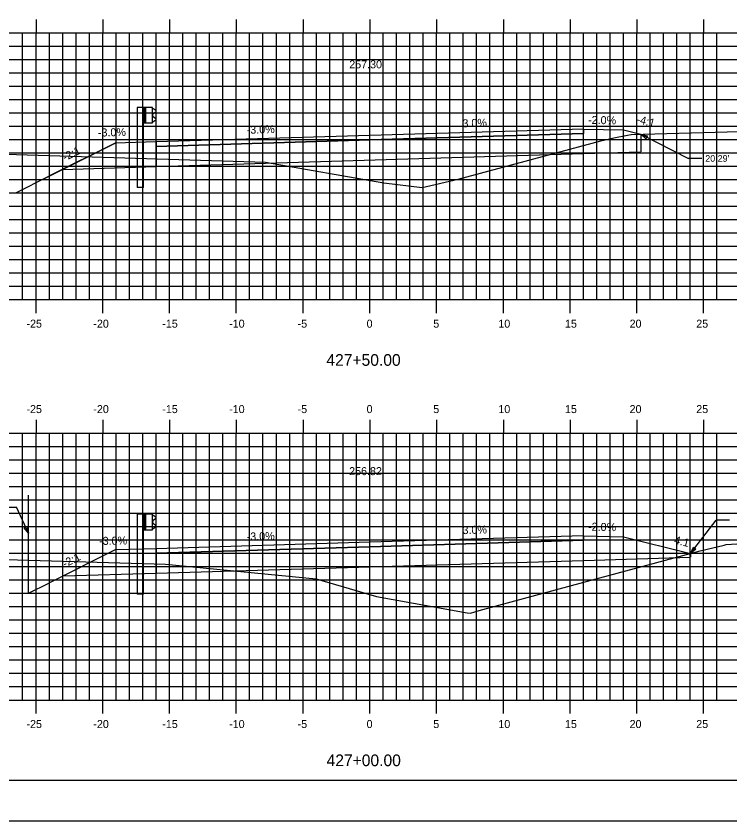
# Model space of a CAD drawing. Extents: x 1160718 to 1173142, y 616002 to 617630.
# Drawn here: x 1170822.9 to 1170876.4, y 616613.9 to 616674.2 of the extents above; entities that cross this region are included whole.
import ezdxf

# ---------------------------------------------------------------- set-up
doc = ezdxf.new("R2010")
doc.units = 0
for name, color, linetype in [('ANNOTATION', 7, 'Continuous'), ('BORDER', 7, 'Continuous'), ('D_Guardrail_Beam_Lt', 7, 'Continuous'), ('D_Roadway_Centerline', 7, 'Continuous'), ('D_Roadway_Centerline_Text', 7, 'Continuous'), ('D_Roadway_Edge_Pavement', 7, 'Continuous'), ('D_Roadway_Edge_Shoulder', 7, 'Continuous'), ('D_Roadway_Edge_TW', 7, 'Continuous'), ('D_Roadway_Pavement', 7, 'Continuous'), ('D_Roadway_SlopeLines', 7, 'Continuous'), ('D_Roadway_SubGrade', 7, 'Continuous'), ('H_V ANNOTATION', 7, 'Continuous'), ('MAJOR', 7, 'Continuous'), ('MINOR', 7, 'Continuous'), ('PLOT BOUNDARY', 7, 'Continuous'), ('S_Roadway_Centerline', 7, 'Continuous'), ('SHADING', 7, 'Continuous')]:
    doc.layers.add(name, color=color, linetype=linetype)

msp = doc.modelspace()

# ---------------------------------------------------------------- linework, layer by layer
at = {"layer": 'ANNOTATION'}
for p, q in [((1170869.707, 616665.327), (1170873.292, 616663.506)), ((1170874.292, 616663.506), (1170873.292, 616663.506)), ((1170821.96, 616637.377), (1170822.96, 616637.377)), ((1170823.863, 616635.436), (1170822.96, 616637.377)), ((1170873.445, 616633.911), (1170875.353, 616636.405)), ((1170876.353, 616636.405), (1170875.353, 616636.405))]:
    msp.add_line(p, q, dxfattribs=at)
for points in [[(1170870.096, 616664.989), (1170869.707, 616665.327), (1170870.209, 616665.212)], [(1170823.765, 616635.942), (1170823.863, 616635.436), (1170823.538, 616635.837)], [(1170873.848, 616634.232), (1170873.445, 616633.911), (1170873.649, 616634.384)]]:
    msp.add_lwpolyline(points, close=True, dxfattribs=at)
at = {"layer": 'BORDER'}
msp.add_line((1170774.42, 616616.928), (1170934.42, 616616.928), dxfattribs=at)
at = {"layer": 'D_Guardrail_Beam_Lt'}
for p, q in [((1170831.99, 616667.332), (1170831.99, 616661.332)), ((1170832.461, 616667.332), (1170831.99, 616667.332)), ((1170833.148, 616667.332), (1170832.461, 616667.332)), ((1170832.461, 616667.332), (1170832.461, 616666.165)), ((1170832.523, 616667.332), (1170832.523, 616666.165)), ((1170832.627, 616667.332), (1170832.627, 616666.165)), ((1170833.148, 616666.165), (1170833.148, 616667.332)), ((1170833.148, 616667.249), (1170833.222, 616667.234)), ((1170833.382, 616666.984), (1170833.186, 616666.848)), ((1170833.238, 616667.227), (1170833.382, 616667.127)), ((1170833.222, 616666.263), (1170833.148, 616666.249)), ((1170833.152, 616666.784), (1170833.152, 616666.714)), ((1170833.186, 616666.649), (1170833.382, 616666.513)), ((1170833.382, 616666.37), (1170833.238, 616666.27)), ((1170832.461, 616666.165), (1170833.148, 616666.165)), ((1170832.481, 616661.332), (1170832.481, 616666.165)), ((1170832.481, 616661.332), (1170831.99, 616661.332)), ((1170831.989, 616636.851), (1170831.989, 616630.851)), ((1170832.46, 616636.851), (1170831.989, 616636.851)), ((1170833.148, 616636.851), (1170832.46, 616636.851)), ((1170832.46, 616636.851), (1170832.46, 616635.684)), ((1170832.523, 616636.851), (1170832.523, 616635.684)), ((1170832.627, 616636.851), (1170832.627, 616635.684)), ((1170833.148, 616635.684), (1170833.148, 616636.851)), ((1170833.148, 616636.767), (1170833.222, 616636.753)), ((1170833.238, 616636.746), (1170833.381, 616636.646)), ((1170833.152, 616636.302), (1170833.152, 616636.232)), ((1170833.381, 616636.503), (1170833.186, 616636.367)), ((1170833.186, 616636.168), (1170833.381, 616636.032)), ((1170832.46, 616635.684), (1170833.148, 616635.684)), ((1170832.481, 616630.851), (1170832.481, 616635.684)), ((1170833.222, 616635.782), (1170833.148, 616635.767)), ((1170833.381, 616635.888), (1170833.238, 616635.788)), ((1170832.481, 616630.851), (1170831.989, 616630.851))]:
    msp.add_line(p, q, dxfattribs=at)
for centre, major_axis, start_param, end_param in [((1170833.214, 616667.193), (0.0417, 0), 0.959931, 1.376053), ((1170833.331, 616667.056), (0.0877, 0), 5.323254, 7.243116), ((1170833.231, 616666.784), (-0.0789, 0), 5.323254, 6.283185), ((1170833.231, 616666.714), (-0.0789, 0), 6.283185, 7.243116), ((1170833.214, 616666.304), (0.0417, 0), 4.907132, 5.323254), ((1170833.331, 616666.441), (0.0877, 0), 5.323254, 7.243116), ((1170833.214, 616636.712), (0.0417, 0), 0.959931, 1.376053), ((1170833.231, 616636.302), (-0.0789, 0), 5.323254, 6.283185), ((1170833.231, 616636.232), (-0.0789, 0), 6.283185, 7.243116), ((1170833.331, 616636.574), (0.0877, 0), 5.323254, 7.243116), ((1170833.214, 616635.822), (0.0417, 0), 4.907132, 5.323254), ((1170833.331, 616635.96), (0.0877, 0), 5.323254, 7.243116)]:
    msp.add_ellipse(centre, major_axis=major_axis, ratio=0.995501, start_param=start_param, end_param=end_param, dxfattribs=at)
at = {"layer": 'D_Roadway_Centerline'}
for points in [[(1170822.9, 616660.928), (1170825.392, 616662.175), (1170830.356, 616664.657)], [(1170824.9, 616661.928), (1170824.9, 616661.928), (1170830.356, 616664.657)]]:
    msp.add_lwpolyline(points, dxfattribs=at)
at = {"layer": 'D_Roadway_Edge_Pavement'}
msp.add_lwpolyline([(1170779.42, 616630.928), (1170823.863, 616630.928), (1170825.392, 616631.693)], dxfattribs=at)
at = {"layer": 'D_Roadway_Edge_Shoulder'}
for points in [[(1170865.42, 616665.709), (1170865.42, 616665.375)], [(1170833.42, 616664.749), (1170833.42, 616664.415)], [(1170865.42, 616635.227), (1170865.42, 616634.894)], [(1170833.42, 616634.267), (1170833.42, 616633.934)]]:
    msp.add_lwpolyline(points, dxfattribs=at)
at = {"layer": 'D_Roadway_Edge_TW'}
for points in [[(1170865.42, 616665.375), (1170865.42, 616665.709), (1170849.42, 616665.229), (1170833.42, 616664.749), (1170833.42, 616664.415), (1170849.42, 616664.895)], [(1170865.42, 616634.894), (1170865.42, 616635.227), (1170849.42, 616634.747), (1170833.42, 616634.267), (1170833.42, 616633.934), (1170849.42, 616634.414)]]:
    msp.add_lwpolyline(points, close=True, dxfattribs=at)
at = {"layer": 'D_Roadway_Pavement'}
for p, q in [((1170833.42, 616664.749), (1170830.356, 616664.657)), ((1170823.863, 616630.928), (1170823.863, 616638.285)), ((1170833.42, 616634.267), (1170830.356, 616634.175))]:
    msp.add_line(p, q, dxfattribs=at)
for points in [[(1170865.42, 616665.375), (1170865.42, 616665.375), (1170849.42, 616664.895), (1170833.42, 616664.415), (1170833.42, 616664.415), (1170849.42, 616664.895)], [(1170865.42, 616634.894), (1170865.42, 616634.894), (1170849.42, 616634.414), (1170833.42, 616633.934), (1170833.42, 616633.934), (1170849.42, 616634.414)]]:
    msp.add_lwpolyline(points, close=True, dxfattribs=at)
for points in [[(1170865.42, 616665.375), (1170865.42, 616665.375)], [(1170865.42, 616665.375), (1170865.42, 616665.375)], [(1170833.42, 616664.415), (1170833.42, 616664.415)], [(1170833.42, 616664.415), (1170833.42, 616664.415)], [(1170865.42, 616634.894), (1170865.42, 616634.894)], [(1170865.42, 616634.894), (1170865.42, 616634.894)], [(1170833.42, 616633.934), (1170833.42, 616633.934)], [(1170833.42, 616633.934), (1170833.42, 616633.934)]]:
    msp.add_lwpolyline(points, dxfattribs=at)
at = {"layer": 'D_Roadway_SlopeLines'}
for points in [[(1170868.42, 616665.649), (1170869.707, 616665.327)], [(1170830.356, 616664.657), (1170824.9, 616661.928)], [(1170868.42, 616635.167), (1170873.445, 616633.911)]]:
    msp.add_lwpolyline(points, dxfattribs=at)
at = {"layer": 'D_Roadway_SubGrade'}
for p, q in [((1170865.42, 616665.709), (1170868.42, 616665.649)), ((1170865.42, 616663.876), (1170865.42, 616665.709)), ((1170865.42, 616665.375), (1170849.42, 616664.895)), ((1170865.42, 616663.876), (1170865.42, 616665.375)), ((1170868.42, 616665.649), (1170869.707, 616665.327)), ((1170869.707, 616665.327), (1170869.707, 616664.004)), ((1170830.356, 616664.657), (1170825.392, 616662.175)), ((1170849.42, 616664.895), (1170833.42, 616664.415)), ((1170833.42, 616662.916), (1170833.42, 616664.749)), ((1170833.42, 616664.415), (1170833.42, 616662.916)), ((1170865.42, 616635.227), (1170868.42, 616635.167)), ((1170865.42, 616633.394), (1170865.42, 616635.227)), ((1170868.42, 616635.167), (1170873.445, 616633.911)), ((1170849.42, 616634.414), (1170833.42, 616633.934)), ((1170865.42, 616634.894), (1170849.42, 616634.414)), ((1170865.42, 616633.394), (1170865.42, 616634.894)), ((1170830.356, 616634.175), (1170825.392, 616631.693)), ((1170833.42, 616632.434), (1170833.42, 616634.267)), ((1170833.42, 616633.934), (1170833.42, 616632.434)), ((1170873.445, 616633.911), (1170873.445, 616633.635))]:
    msp.add_line(p, q, dxfattribs=at)
at = {"layer": 'MAJOR'}
for p, q in [((1170824.42, 616673.93), (1170824.42, 616672.928)), ((1170829.42, 616673.93), (1170829.42, 616672.928)), ((1170834.42, 616673.93), (1170834.42, 616672.928)), ((1170839.42, 616673.93), (1170839.42, 616672.928)), ((1170844.42, 616673.93), (1170844.42, 616672.928)), ((1170849.42, 616673.93), (1170849.42, 616672.928)), ((1170854.42, 616673.93), (1170854.42, 616672.928)), ((1170859.42, 616673.93), (1170859.42, 616672.928)), ((1170864.42, 616673.93), (1170864.42, 616672.928)), ((1170869.42, 616673.93), (1170869.42, 616672.928)), ((1170874.42, 616673.93), (1170874.42, 616672.928)), ((1170779.42, 616672.928), (1170919.42, 616672.928)), ((1170779.42, 616672.928), (1170919.42, 616672.928)), ((1170824.42, 616652.928), (1170824.42, 616672.928)), ((1170829.42, 616652.928), (1170829.42, 616672.928)), ((1170834.42, 616652.928), (1170834.42, 616672.928)), ((1170839.42, 616652.928), (1170839.42, 616672.928)), ((1170844.42, 616652.928), (1170844.42, 616672.928)), ((1170849.42, 616652.928), (1170849.42, 616672.928)), ((1170854.42, 616652.928), (1170854.42, 616672.928)), ((1170859.42, 616652.928), (1170859.42, 616672.928)), ((1170864.42, 616652.928), (1170864.42, 616672.928)), ((1170869.42, 616652.928), (1170869.42, 616672.928)), ((1170874.42, 616652.928), (1170874.42, 616672.928)), ((1170779.42, 616667.928), (1170919.42, 616667.928)), ((1170779.42, 616662.928), (1170919.42, 616662.928)), ((1170779.42, 616657.928), (1170919.42, 616657.928)), ((1170779.42, 616652.928), (1170919.42, 616652.928)), ((1170779.42, 616652.928), (1170919.42, 616652.928)), ((1170824.42, 616651.926), (1170824.42, 616652.928)), ((1170829.42, 616651.926), (1170829.42, 616652.928)), ((1170834.42, 616651.926), (1170834.42, 616652.928)), ((1170839.42, 616651.926), (1170839.42, 616652.928)), ((1170844.42, 616651.926), (1170844.42, 616652.928)), ((1170849.42, 616651.926), (1170849.42, 616652.928)), ((1170854.42, 616651.926), (1170854.42, 616652.928)), ((1170859.42, 616651.926), (1170859.42, 616652.928)), ((1170864.42, 616651.926), (1170864.42, 616652.928)), ((1170869.42, 616651.926), (1170869.42, 616652.928)), ((1170874.42, 616651.926), (1170874.42, 616652.928)), ((1170824.42, 616643.93), (1170824.42, 616642.928)), ((1170829.42, 616643.93), (1170829.42, 616642.928)), ((1170834.42, 616643.93), (1170834.42, 616642.928)), ((1170839.42, 616643.93), (1170839.42, 616642.928)), ((1170844.42, 616643.93), (1170844.42, 616642.928)), ((1170849.42, 616643.93), (1170849.42, 616642.928)), ((1170854.42, 616643.93), (1170854.42, 616642.928)), ((1170859.42, 616643.93), (1170859.42, 616642.928)), ((1170864.42, 616643.93), (1170864.42, 616642.928)), ((1170869.42, 616643.93), (1170869.42, 616642.928)), ((1170874.42, 616643.93), (1170874.42, 616642.928)), ((1170779.42, 616642.928), (1170919.42, 616642.928)), ((1170779.42, 616642.928), (1170919.42, 616642.928)), ((1170824.42, 616622.928), (1170824.42, 616642.928)), ((1170829.42, 616622.928), (1170829.42, 616642.928)), ((1170834.42, 616622.928), (1170834.42, 616642.928)), ((1170839.42, 616622.928), (1170839.42, 616642.928)), ((1170844.42, 616622.928), (1170844.42, 616642.928)), ((1170849.42, 616622.928), (1170849.42, 616642.928)), ((1170854.42, 616622.928), (1170854.42, 616642.928)), ((1170859.42, 616622.928), (1170859.42, 616642.928)), ((1170864.42, 616622.928), (1170864.42, 616642.928)), ((1170869.42, 616622.928), (1170869.42, 616642.928)), ((1170874.42, 616622.928), (1170874.42, 616642.928)), ((1170779.42, 616637.928), (1170919.42, 616637.928)), ((1170779.42, 616632.928), (1170919.42, 616632.928)), ((1170823.863, 616630.928), (1170919.42, 616630.928)), ((1170779.42, 616627.928), (1170919.42, 616627.928)), ((1170779.42, 616622.928), (1170919.42, 616622.928)), ((1170779.42, 616622.928), (1170919.42, 616622.928)), ((1170824.42, 616621.926), (1170824.42, 616622.928)), ((1170829.42, 616621.926), (1170829.42, 616622.928)), ((1170834.42, 616621.926), (1170834.42, 616622.928)), ((1170839.42, 616621.926), (1170839.42, 616622.928)), ((1170844.42, 616621.926), (1170844.42, 616622.928)), ((1170849.42, 616621.926), (1170849.42, 616622.928)), ((1170854.42, 616621.926), (1170854.42, 616622.928)), ((1170859.42, 616621.926), (1170859.42, 616622.928)), ((1170864.42, 616621.926), (1170864.42, 616622.928)), ((1170869.42, 616621.926), (1170869.42, 616622.928)), ((1170874.42, 616621.926), (1170874.42, 616622.928))]:
    msp.add_line(p, q, dxfattribs=at)
at = {"layer": 'MINOR'}
for p, q in [((1170823.42, 616652.928), (1170823.42, 616672.928)), ((1170825.42, 616652.928), (1170825.42, 616672.928)), ((1170826.42, 616652.928), (1170826.42, 616672.928)), ((1170827.42, 616652.928), (1170827.42, 616672.928)), ((1170828.42, 616652.928), (1170828.42, 616672.928)), ((1170830.42, 616652.928), (1170830.42, 616672.928)), ((1170831.42, 616652.928), (1170831.42, 616672.928)), ((1170832.42, 616652.928), (1170832.42, 616672.928)), ((1170833.42, 616652.928), (1170833.42, 616672.928)), ((1170835.42, 616652.928), (1170835.42, 616672.928)), ((1170836.42, 616652.928), (1170836.42, 616672.928)), ((1170837.42, 616652.928), (1170837.42, 616672.928)), ((1170838.42, 616652.928), (1170838.42, 616672.928)), ((1170840.42, 616652.928), (1170840.42, 616672.928)), ((1170841.42, 616652.928), (1170841.42, 616672.928)), ((1170842.42, 616652.928), (1170842.42, 616672.928)), ((1170843.42, 616652.928), (1170843.42, 616672.928)), ((1170845.42, 616652.928), (1170845.42, 616672.928)), ((1170846.42, 616652.928), (1170846.42, 616672.928)), ((1170847.42, 616652.928), (1170847.42, 616672.928)), ((1170848.42, 616652.928), (1170848.42, 616672.928)), ((1170850.42, 616652.928), (1170850.42, 616672.928)), ((1170851.42, 616652.928), (1170851.42, 616672.928)), ((1170852.42, 616652.928), (1170852.42, 616672.928)), ((1170853.42, 616652.928), (1170853.42, 616672.928)), ((1170855.42, 616652.928), (1170855.42, 616672.928)), ((1170856.42, 616652.928), (1170856.42, 616672.928)), ((1170857.42, 616652.928), (1170857.42, 616672.928)), ((1170858.42, 616652.928), (1170858.42, 616672.928)), ((1170860.42, 616652.928), (1170860.42, 616672.928)), ((1170861.42, 616652.928), (1170861.42, 616672.928)), ((1170862.42, 616652.928), (1170862.42, 616672.928)), ((1170863.42, 616652.928), (1170863.42, 616672.928)), ((1170865.42, 616652.928), (1170865.42, 616672.928)), ((1170866.42, 616652.928), (1170866.42, 616672.928)), ((1170867.42, 616652.928), (1170867.42, 616672.928)), ((1170868.42, 616652.928), (1170868.42, 616672.928)), ((1170870.42, 616652.928), (1170870.42, 616672.928)), ((1170871.42, 616652.928), (1170871.42, 616672.928)), ((1170872.42, 616652.928), (1170872.42, 616672.928)), ((1170873.42, 616652.928), (1170873.42, 616672.928)), ((1170875.42, 616652.928), (1170875.42, 616672.928)), ((1170779.42, 616671.928), (1170919.42, 616671.928)), ((1170779.42, 616670.928), (1170919.42, 616670.928)), ((1170779.42, 616669.928), (1170919.42, 616669.928)), ((1170779.42, 616668.928), (1170919.42, 616668.928)), ((1170779.42, 616666.928), (1170919.42, 616666.928)), ((1170779.42, 616665.928), (1170919.42, 616665.928)), ((1170779.42, 616664.928), (1170919.42, 616664.928)), ((1170779.42, 616663.928), (1170919.42, 616663.928)), ((1170779.42, 616661.928), (1170919.42, 616661.928)), ((1170779.42, 616660.928), (1170919.42, 616660.928)), ((1170779.42, 616659.928), (1170919.42, 616659.928)), ((1170779.42, 616658.928), (1170919.42, 616658.928)), ((1170779.42, 616656.928), (1170919.42, 616656.928)), ((1170779.42, 616655.928), (1170919.42, 616655.928)), ((1170779.42, 616654.928), (1170919.42, 616654.928)), ((1170779.42, 616653.928), (1170919.42, 616653.928)), ((1170823.42, 616622.928), (1170823.42, 616642.928)), ((1170825.42, 616622.928), (1170825.42, 616642.928)), ((1170826.42, 616622.928), (1170826.42, 616642.928)), ((1170827.42, 616622.928), (1170827.42, 616642.928)), ((1170828.42, 616622.928), (1170828.42, 616642.928)), ((1170830.42, 616622.928), (1170830.42, 616642.928)), ((1170831.42, 616622.928), (1170831.42, 616642.928)), ((1170832.42, 616622.928), (1170832.42, 616642.928)), ((1170833.42, 616622.928), (1170833.42, 616642.928)), ((1170835.42, 616622.928), (1170835.42, 616642.928)), ((1170836.42, 616622.928), (1170836.42, 616642.928)), ((1170837.42, 616622.928), (1170837.42, 616642.928)), ((1170838.42, 616622.928), (1170838.42, 616642.928)), ((1170840.42, 616622.928), (1170840.42, 616642.928)), ((1170841.42, 616622.928), (1170841.42, 616642.928)), ((1170842.42, 616622.928), (1170842.42, 616642.928)), ((1170843.42, 616622.928), (1170843.42, 616642.928)), ((1170845.42, 616622.928), (1170845.42, 616642.928)), ((1170846.42, 616622.928), (1170846.42, 616642.928)), ((1170847.42, 616622.928), (1170847.42, 616642.928)), ((1170848.42, 616622.928), (1170848.42, 616642.928)), ((1170850.42, 616622.928), (1170850.42, 616642.928)), ((1170851.42, 616622.928), (1170851.42, 616642.928)), ((1170852.42, 616622.928), (1170852.42, 616642.928)), ((1170853.42, 616622.928), (1170853.42, 616642.928)), ((1170855.42, 616622.928), (1170855.42, 616642.928)), ((1170856.42, 616622.928), (1170856.42, 616642.928)), ((1170857.42, 616622.928), (1170857.42, 616642.928)), ((1170858.42, 616622.928), (1170858.42, 616642.928)), ((1170860.42, 616622.928), (1170860.42, 616642.928)), ((1170861.42, 616622.928), (1170861.42, 616642.928)), ((1170862.42, 616622.928), (1170862.42, 616642.928)), ((1170863.42, 616622.928), (1170863.42, 616642.928)), ((1170865.42, 616622.928), (1170865.42, 616642.928)), ((1170866.42, 616622.928), (1170866.42, 616642.928)), ((1170867.42, 616622.928), (1170867.42, 616642.928)), ((1170868.42, 616622.928), (1170868.42, 616642.928)), ((1170870.42, 616622.928), (1170870.42, 616642.928)), ((1170871.42, 616622.928), (1170871.42, 616642.928)), ((1170872.42, 616622.928), (1170872.42, 616642.928)), ((1170873.42, 616622.928), (1170873.42, 616642.928)), ((1170875.42, 616622.928), (1170875.42, 616642.928)), ((1170779.42, 616641.928), (1170919.42, 616641.928)), ((1170779.42, 616640.928), (1170919.42, 616640.928)), ((1170779.42, 616639.928), (1170919.42, 616639.928)), ((1170779.42, 616638.928), (1170919.42, 616638.928)), ((1170779.42, 616636.928), (1170919.42, 616636.928)), ((1170779.42, 616635.928), (1170919.42, 616635.928)), ((1170779.42, 616634.928), (1170919.42, 616634.928)), ((1170779.42, 616633.928), (1170919.42, 616633.928)), ((1170779.42, 616631.928), (1170919.42, 616631.928)), ((1170779.42, 616630.928), (1170919.42, 616630.928)), ((1170779.42, 616629.928), (1170919.42, 616629.928)), ((1170779.42, 616628.928), (1170919.42, 616628.928)), ((1170779.42, 616626.928), (1170919.42, 616626.928)), ((1170779.42, 616625.928), (1170919.42, 616625.928)), ((1170779.42, 616624.928), (1170919.42, 616624.928)), ((1170779.42, 616623.928), (1170919.42, 616623.928))]:
    msp.add_line(p, q, dxfattribs=at)
at = {"layer": 'PLOT BOUNDARY'}
msp.add_lwpolyline([(1170766.327, 616613.869), (1170936.327, 616613.869), (1170936.327, 616723.869), (1170766.327, 616723.869)], close=True, dxfattribs=at)
at = {"layer": 'S_Roadway_Centerline'}
for points in [[(1170779.42, 616665.198), (1170781.611, 616665.115), (1170801.067, 616664.568), (1170810.371, 616664.507), (1170819.699, 616663.892), (1170841.601, 616663.226), (1170850.475, 616661.686), (1170853.343, 616661.344), (1170856.046, 616661.968), (1170866.73, 616664.84), (1170867.699, 616665.045), (1170868.716, 616665.251), (1170868.988, 616665.306), (1170871.66, 616665.385), (1170884.356, 616665.721)], [(1170779.42, 616635.074), (1170784.072, 616634.861), (1170802.594, 616634.435), (1170814.467, 616633.692), (1170834.121, 616633.112), (1170845.392, 616632.012), (1170849.929, 616630.686), (1170856.722, 616629.466), (1170856.955, 616629.424), (1170857.609, 616629.63), (1170866.647, 616632.093), (1170874.152, 616634.1), (1170875.958, 616634.539), (1170876.116, 616634.569), (1170879.288, 616634.791)]]:
    msp.add_lwpolyline(points, dxfattribs=at)
at = {"layer": 'SHADING'}
for points in [[(1170826.407, 616662.682), (1170833.408, 616662.915), (1170865.408, 616663.875), (1170869.707, 616664.004)], [(1170826.456, 616632.225), (1170833.42, 616632.434), (1170865.42, 616633.394), (1170873.445, 616633.635)]]:
    msp.add_lwpolyline(points, dxfattribs=at)

# ---------------------------------------------------------------- texts
at = {"layer": 'ANNOTATION'}
for s, rotation, p in [('3.0%', 1.71836, (1170856.369, 616665.838)), ('-2.0%', 358.85424, (1170865.763, 616666.102)), ('-4:1', 345.96376, (1170869.351, 616666.181)), ('-3.0%', 1.14576, (1170829.064, 616665.148)), ('-3.0%', 1.71836, (1170840.208, 616665.353)), ('-2:1', 26.56505, (1170826.589, 616663.291)), ('-2.0%', 358.85424, (1170865.763, 616635.621)), ('-3.0%', 1.71836, (1170840.208, 616634.871)), ('3.0%', 1.71836, (1170856.369, 616635.356)), ('-3.0%', 1.14576, (1170829.152, 616634.543)), ('-4:1', 345.96376, (1170871.916, 616634.724)), ('-2:1', 26.56505, (1170826.589, 616632.839))]:
    msp.add_text(s, height=0.6, rotation=rotation, dxfattribs=at).set_placement(p)
msp.add_text("20.29'", height=0.5, dxfattribs=at).set_placement((1170874.542, 616663.256))
at = {"layer": 'D_Roadway_Centerline'}
for s, p in [('C', (1170849.415, 616665.229)), ('L', (1170849.42, 616665.221)), ('C', (1170849.415, 616634.747)), ('L', (1170849.42, 616634.74))]:
    msp.add_text(s, height=0.0146, dxfattribs=at).set_placement(p)
at = {"layer": 'D_Roadway_Centerline_Text'}
for s, p in [('257.30', (1170847.879, 616670.261)), ('256.82', (1170847.871, 616639.779))]:
    msp.add_text(s, height=0.6, dxfattribs=at).set_placement(p)
at = {"layer": 'H_V ANNOTATION'}
for s, height, p in [('-25', 0.6, (1170823.706, 616650.828)), ('-20', 0.6, (1170828.714, 616650.828)), ('-15', 0.6, (1170833.877, 616650.828)), ('-10', 0.6, (1170838.885, 616650.828)), ('-5', 0.6, (1170844.011, 616650.828)), ('0', 0.6, (1170849.179, 616650.828)), ('5', 0.6, (1170854.171, 616650.828)), ('10', 0.6, (1170859.046, 616650.828)), ('15', 0.6, (1170864.038, 616650.828)), ('20', 0.6, (1170868.874, 616650.828)), ('25', 0.6, (1170873.866, 616650.828)), ('427+50.00', 0.875, (1170846.166, 616647.971)), ('-25', 0.6, (1170823.706, 616644.428)), ('-20', 0.6, (1170828.714, 616644.428)), ('-15', 0.6, (1170833.877, 616644.428)), ('-10', 0.6, (1170838.885, 616644.428)), ('-5', 0.6, (1170844.011, 616644.428)), ('0', 0.6, (1170849.179, 616644.428)), ('5', 0.6, (1170854.171, 616644.428)), ('10', 0.6, (1170859.046, 616644.428)), ('15', 0.6, (1170864.038, 616644.428)), ('20', 0.6, (1170868.874, 616644.428)), ('25', 0.6, (1170873.866, 616644.428)), ('-25', 0.6, (1170823.706, 616620.828)), ('-20', 0.6, (1170828.714, 616620.828)), ('-15', 0.6, (1170833.877, 616620.828)), ('-10', 0.6, (1170838.885, 616620.828)), ('-5', 0.6, (1170844.011, 616620.828)), ('0', 0.6, (1170849.179, 616620.828)), ('5', 0.6, (1170854.171, 616620.828)), ('10', 0.6, (1170859.046, 616620.828)), ('15', 0.6, (1170864.038, 616620.828)), ('20', 0.6, (1170868.874, 616620.828)), ('25', 0.6, (1170873.866, 616620.828)), ('427+00.00', 0.875, (1170846.182, 616617.971))]:
    msp.add_text(s, height=height, dxfattribs=at).set_placement(p)

doc.saveas('drawing.dxf')
